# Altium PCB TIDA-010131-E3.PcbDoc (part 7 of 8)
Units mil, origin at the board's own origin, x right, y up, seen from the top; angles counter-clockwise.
Board outline 6889.76 x 5118.11 mil, 6 copper layers (Top Layer, GND Layer, Signal Layer 1, Signal Layer 2, PWR Layer, Bottom Layer), stack 58.5 mil thick; 758 components, 455 nets, 2194 pads, 1156 vias.
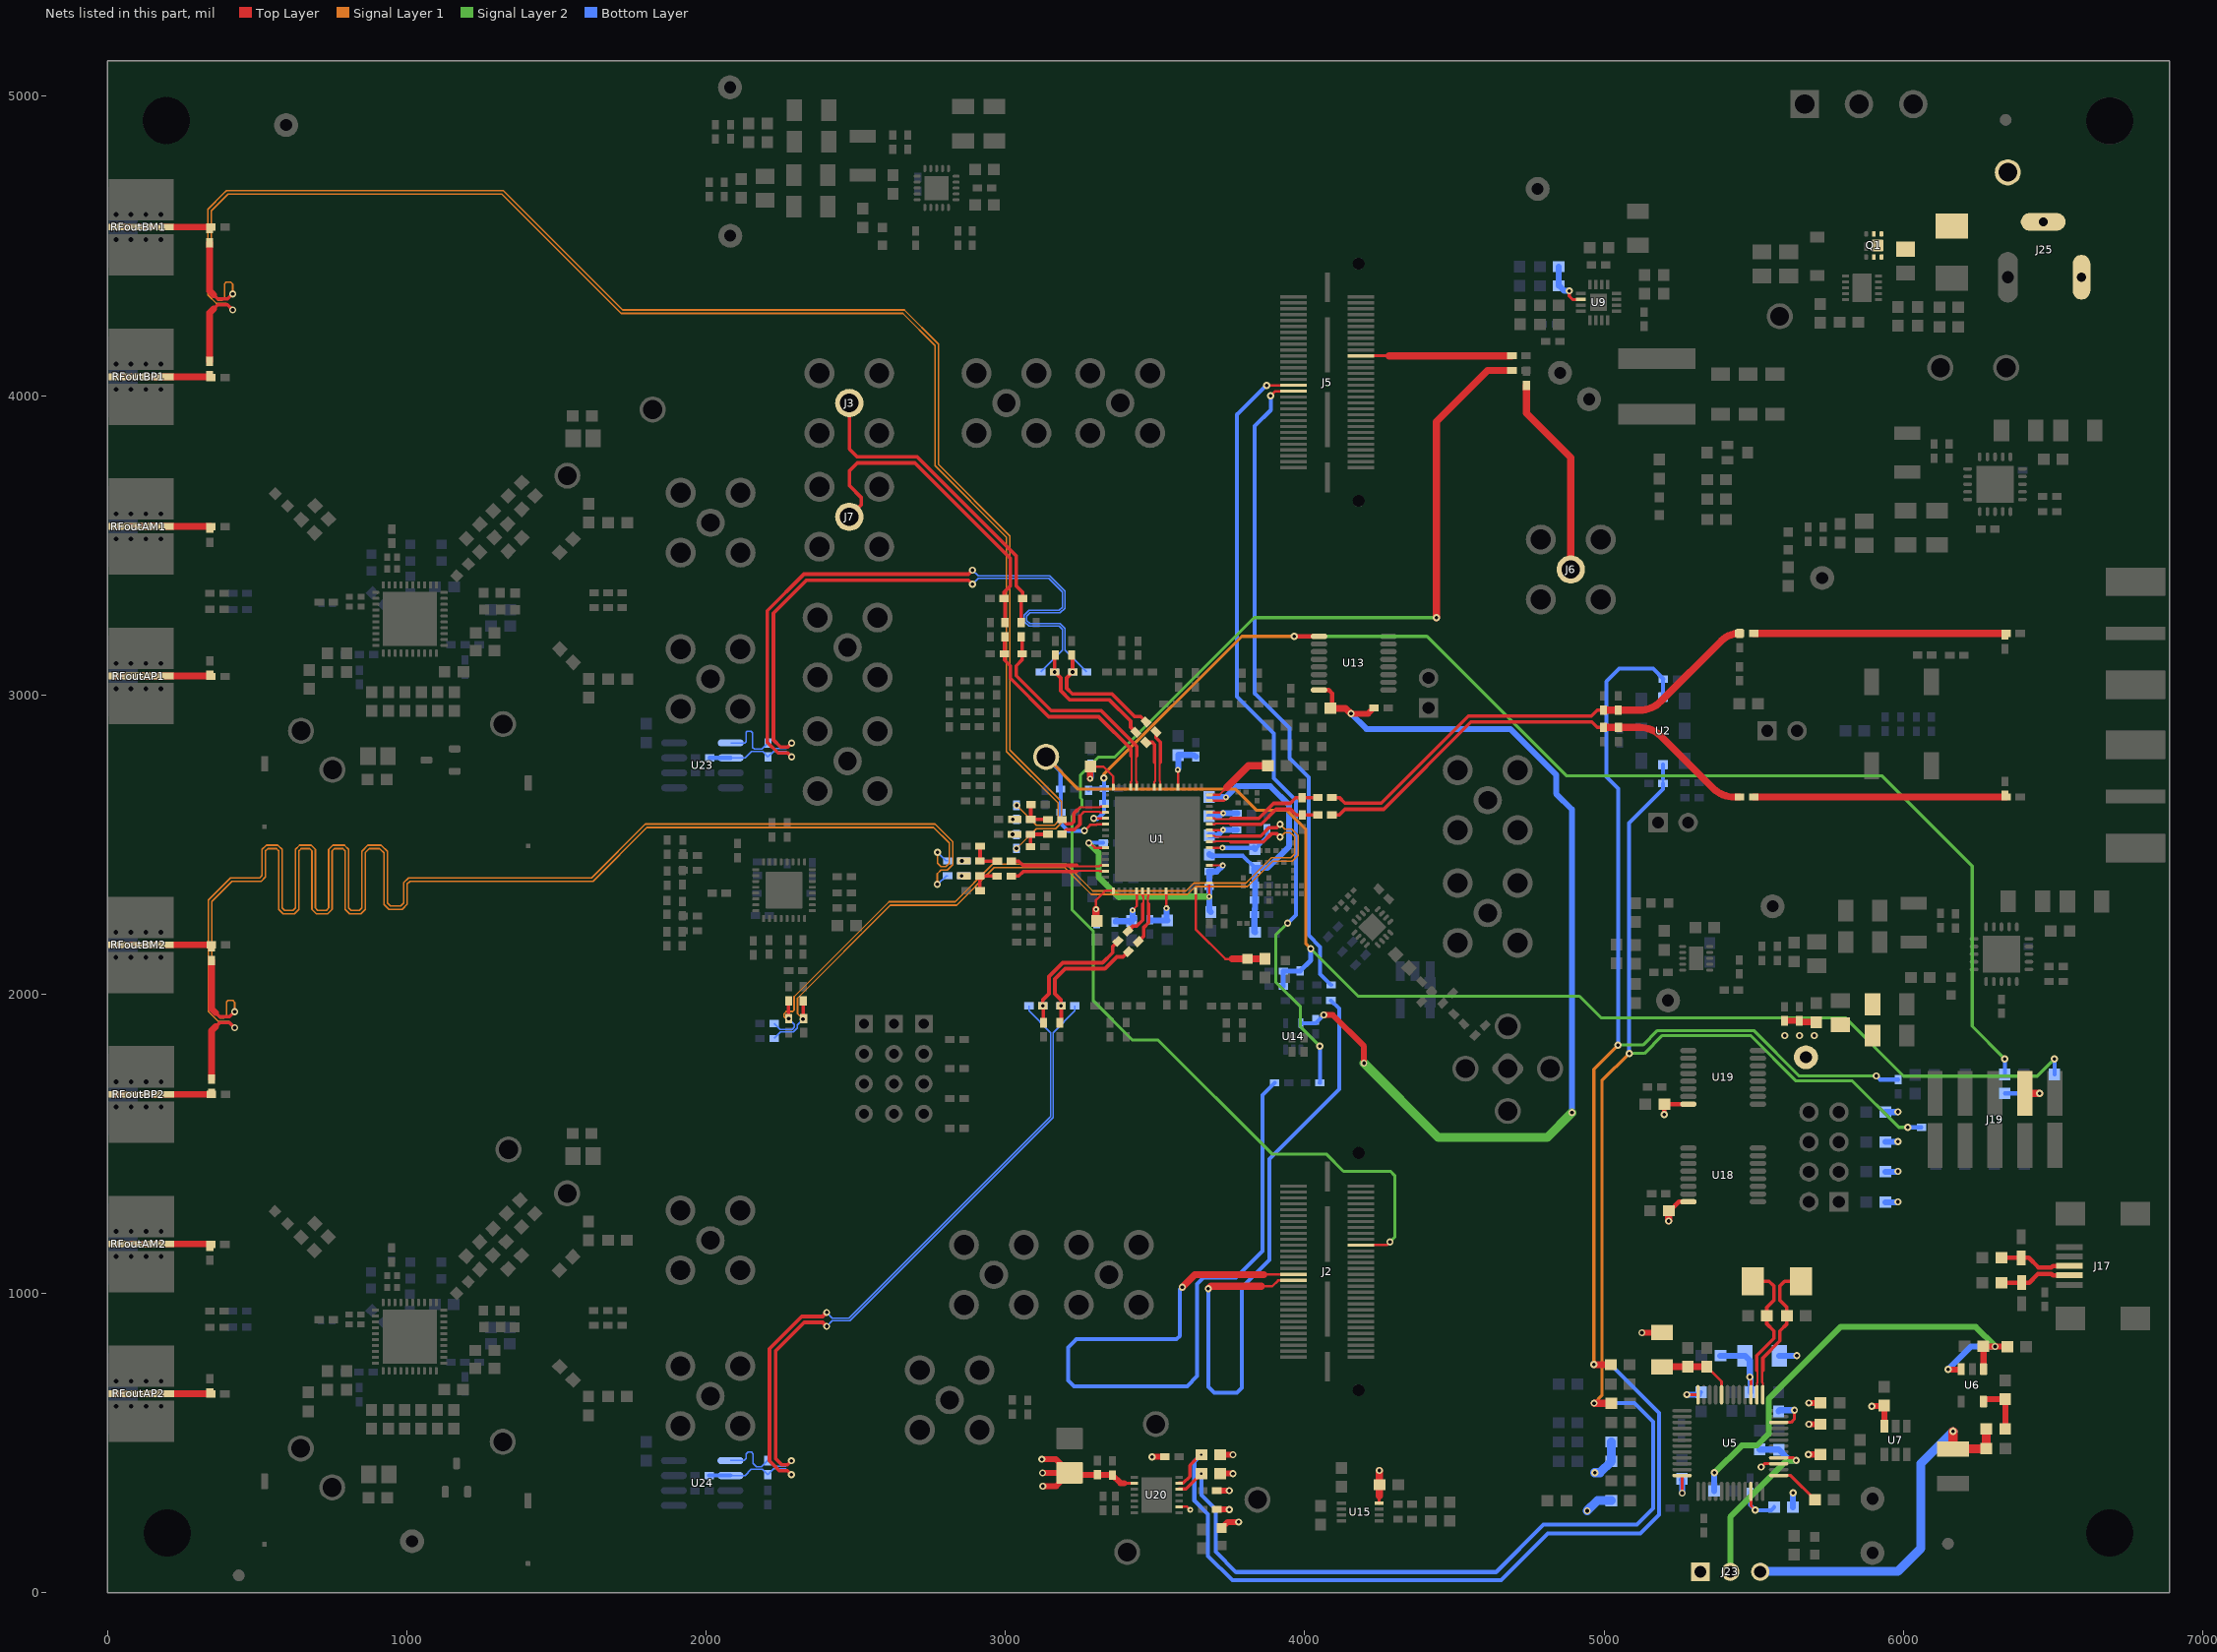
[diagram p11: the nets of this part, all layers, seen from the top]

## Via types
v1: diameter 24, hole 12, Top Layer to Bottom Layer, 726 vias
v2: diameter 32, hole 16, Top Layer to Bottom Layer, 311 vias
v3: diameter 19.68, hole 7.87, Top Layer to Bottom Layer, 117 vias
v4: diameter 25, hole 10, Top Layer to Bottom Layer, 2 vias

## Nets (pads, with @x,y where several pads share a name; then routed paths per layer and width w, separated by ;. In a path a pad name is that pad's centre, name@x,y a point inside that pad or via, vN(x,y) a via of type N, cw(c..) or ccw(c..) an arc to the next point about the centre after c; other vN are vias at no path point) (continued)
OSCI: C125.2 U5.1 Y2.1 | length 485.9
  Top Layer w7: U5.1@5530.47,661.44 5530.47,700.42 5528.13,702.76 5528.13,740.02 5530.63,742.52
  Top Layer w12: 5530.63,742.52 5530.63,784.44 5587.51,841.33 5587.51,874.73 5611.02,898.23 C125.2@5611.02,925.93 5611.02,953.63 5587.51,977.14 5587.51,1025.02 5603.43,1040.93 Y2.1@5658.22,1040.93
OSCIN+: C12.2 R38.2 R40.2 R199.2 | length 1586.9
  Top Layer w12: C12.2@4090.69,2599.1 4115.44,2599.1 4134.32,2617.98 4264.26,2617.98 4555.46,2909.18 4959.31,2909.18 4977.26,2891.22 R40.2@4998.07,2891.22
  Top Layer w24: R40.2@4998.07,2891.22 R199.2@5048.07,2891.22 5119.87,2891.22 cw(c5119.87,2791.22) 5190.58,2861.93 5364.63,2687.89 ccw(c5435.34,2758.6) 5435.34,2658.6 R38.2@5453.07,2658.6 ; R199.2@5047.07,2891.22 R199.2@5047.82,2890.79
OSCIN-: C9.2 C179.2 R34.2 R36.2 R198.2 | length 1597.3
  Top Layer w12: C9.2@4090.69,2656.86 4115.44,2656.86 4134.32,2637.98 4255.98,2637.98 4547.18,2929.18 4957.46,2929.18 4977.26,2948.98 R34.2@4998.07,2948.98
  Top Layer w24: R34.2@4998.07,2948.98 R198.2@5047.07,2948.98 5118.87,2948.98 ccw(c5118.87,3048.98) 5189.58,2978.27 5391.38,3180.07 cw(c5453.07,3118.37) C179.2@5453.07,3205.62
OSCIN_N: C9.1 C11.2 U1.44 | length 393.1
  Top Layer w7: U1.44@3681.05,2587.51 3699.37,2587.51 3701.71,2585.17 3751,2585.17 3753.5,2587.67
  Top Layer w12: 3753.5,2587.67 3846.39,2587.67 3896.4,2637.69 3952.04,2637.69 3970.41,2656.07 C11.2@3991.22,2656.07 4042.66,2656.07 C9.1@4043.45,2656.86
OSCIN_P: C12.1 C22.2 U1.43 | length 392.8
  Top Layer w7: U1.43@3681.05,2567.83 3699.37,2567.83 3701.71,2570.17 3751,2570.17 3753.5,2567.67
  Top Layer w12: 3753.5,2567.67 3854.67,2567.67 3904.69,2617.69 3953.04,2617.69 3971.41,2599.31 C22.2@3992.22,2599.31 4043.24,2599.31 C12.1@4043.45,2599.1
OSCO: C126.1 U5.2 Y2.2 | length 485.9
  Top Layer w7: 5510.63,742.52 5513.13,740.02 5513.13,702.76 5510.78,700.42 U5.2@5510.78,661.44
  Top Layer w12: Y2.2@5496.81,1040.93 5551.6,1040.93 5567.51,1025.02 5567.51,977.14 5544.01,953.63 C126.1@5544.01,925.93 5544.01,898.23 5567.51,874.73 5567.51,849.62 5510.63,792.73 5510.63,742.52
OSCOUT_N: R250.1 R265.2 R269.2 U1.41 | length 2606.1
  Top Layer w7: U1.41@3681.05,2528.46 3699.37,2528.46 3701.71,2526.12 3751,2526.12 3753.5,2528.62
  Top Layer w12: R250.1@2324.82,1977.28 2324.82,1920.03 R269.2@2326.07,1918.78 ; 3753.5,2528.62 3853.33,2528.62 3880.63,2555.91 3906.72,2555.91 v1(3917.97,2567.16)
  Signal Layer 1 w5.5: v1(2323.57,1917.16) 2305.69,1935.03 2305.69,1986.69 2616,2297 2837,2297 2962.5,2422.5 3198.24,2422.5 3287.24,2333.5 3608.5,2333.5 3619,2344 3634.75,2359.75 3808.75,2359.75 3893.5,2444.5 3958.76,2444.5 3978,2463.74 3978,2530.42 3956.76,2551.66 3933.47,2551.66 v1(3917.97,2567.16)
  Bottom Layer w4.25: R265.2@2227.56,1851.91 2249.06,1873.41 2291.21,1873.41 2304.19,1886.38 2304.19,1897.78 v1(2323.57,1917.16)
OSCOUT_P: R244.1 R263.2 R267.2 U1.40 | length 2603.9
  Top Layer w7: U1.40@3681.05,2508.77 3699.37,2508.77 3701.71,2511.12 3751,2511.12 3753.5,2508.62
  Top Layer w12: R244.1@2275.82,1977.28 2275.82,1919.03 R267.2@2276.07,1918.78 ; 3753.5,2508.62 3861.62,2508.62 3888.91,2535.91 3906.72,2535.91 v1(3917.97,2524.66)
  Signal Layer 1 w5.5: v1(2276.32,1917.91) 2267.09,1917.91 2260,1925 2260,1934 2268,1942 2290.19,1942 2294.19,1946 2294.19,1991.46 2611.24,2308.5 2832.24,2308.5 2957.74,2434 3203,2434 3292,2345 3603.74,2345 3629.99,2371.25 3803.99,2371.25 3888.74,2456 3954,2456 3966.5,2468.5 3966.5,2525.66 3952,2540.16 3933.47,2540.16 v1(3917.97,2524.66)
  Bottom Layer w4.25: R263.2@2227.56,1901.91 2247.56,1881.91 2287.69,1881.91 2295.69,1889.91 2295.69,1898.53 v1(2276.32,1917.91)
OUT_N: R36.1 R37.1 R45.2 | length 841.2
  Top Layer w12: R45.2@6334.84,3205.6 R45.2@6339.55,3200.9
  Top Layer w24: R36.1@5500.31,3205.62 R45.2@6334.84,3205.6
OUT_P: R38.1 R39.1 R46.2 | length 842.8
  Top Layer w24: R38.1@5500.31,2658.6 R39.1@6343.15,2658.59
PCLK: J6.1 R260.1 | length 676.7
  Top Layer w24: R260.1@4741,4034.38 4741,3941 4889,3793 J6.1@4889,3419
PCLK1: J5.22 R259.2 | length 504.1
  Top Layer w10: J5.22@4188.32,4132.96 4281.68,4132.96
  Top Layer w24: 4281.68,4132.96 R259.2@4692.38,4133 R259.2@4692.38,4133
PCLK2: J2.22 R261.2 | length 4763.4
  Top Layer w8: J2.22@4188.32,1161.61 4274.93,1161.61 v1(4284.97,1171.66)
  Top Layer w24: v1(4440,3258) 4440,3913 4611,4084 R261.2@4692.38,4084
  Signal Layer 2 w10.5: v1(4284.97,1171.66) 4301,1187.69 4301,1394 4287,1408 4130,1408 4072,1466 3891,1466 3510,1847 3424,1847 3294,1977 3294,2210 3223,2281 3223,2595 3255.85,2627.85 3255.85,2650.59 3251,2655.44 3251,2732 3311,2792 3365,2792 3831,3258 v1(4440,3258)
PGND: C131.2 D8.1 J25.2 J25.3 Q1.1 Q1.2 Q1.5 Q1.6 Q1.8 TP7.1
R_ELMK_SDO: J19.3 R305.2 R311.2 | length 165.2
  Top Layer w24: J19.3@6406,1669 v1(6455,1669)
  Bottom Layer w13.5: R311.2@6339,1668.5 R305.2@6403,1668.5 6454.5,1668.5 v1(6455,1669)
RESET: C184.1 R35.2 R311.1 R343.1 U1.5 U13.9 | length 4502.8
  Top Layer w8: v1(3295,2587.51) U1.5@3334.6,2587.51
  Top Layer w13.5: v1(3965.27,3195.54) U13.9@4047.72,3195.54
  Signal Layer 2 w10.5: v1(3965.27,3195.54) 4408.46,3195.54 4874,2730 5928,2730 6230,2428 6230,1893 v1(6339,1784)
  Signal Layer 1 w10.5: v1(3329,2722) 3329,2734.69 3789.86,3195.54 v1(3965.27,3195.54)
  Bottom Layer w13.5: R343.1@3278,2681.31 3283.35,2686.66 R35.2@3330.35,2686.66 ; v1(3295,2587.51) 3304.43,2587.51 3307.29,2584.66 3329.79,2607.16 C184.1@3329.79,2636.85 ; v1(3329,2722) 3330.35,2720.65 R35.2@3330.35,2686.66 ; C184.1@3329.79,2637.93 C184.1@3329.79,2636.85 ; R311.1@6339,1731.5 v1(6339,1784) ; C184.1@3329.79,2636.85 3330.35,2637.42 R35.2@3330.35,2686.66
RFOUTAM1: C48.1 R84.1 RFoutAM1.1 | length 233.5
  Top Layer w22: RFoutAM1.1@112.65,3562.93 343.46,3562.93 cw(c343.46,3559.45) C48.1@345.92,3561.91
RFOUTAM2: C81.1 R117.1 RFoutAM2.1 | length 235.7
  Top Layer w22: RFoutAM2.1@113.38,1165.1 344.07,1165.1 345.66,1163.51 ccw(c343.2,1161.05) R117.1@343.2,1164.53
RFOUTAP1: C44.1 R81.1 RFoutAP1.1 | length 230.8
  Top Layer w22: RFoutAP1.1@112.65,3063 C44.1@343.46,3063
RFOUTAP2: C77.1 R114.1 RFoutAP2.1 | length 229.7
  Top Layer w22: RFoutAP2.1@113.38,665.1 339.18,665.1 R114.1@341.97,667.89
RFOUTBM1: C57.1 R92.1 RFoutBM1.1 | length 232.7
  Top Layer w22: RFoutBM1.1@112.65,4562.93 C57.1@345.34,4562.93
RFOUTBM2: C90.1 R125.1 RFoutBM2.1 | length 232.7
  Top Layer w22: RFoutBM2.1@112.39,2164.53 R125.1@345.08,2164.53
RFOUTBP1: C64.1 R98.1 RFoutBP1.1 | length 232.7
  Top Layer w22: RFoutBP1.1@112.65,4062.93 345.23,4062.93 C64.1@345.34,4062.82
RFOUTBP2: C97.1 R131.1 RFoutBP2.1 | length 236.5
  Top Layer w22: RFoutBP2.1@113.38,1665.1 344.46,1665.1 R131.1@348.21,1668.85 ; R131.1@344.97,1664.53 R131.1@345.08,1664.42
SCL: R43.1 R172.1 R178.2 R321.1 U2.8 U20.13 | length 6454.5
  Top Layer w11: U20.13@3580.38,366.17 3593.69,366.17 3616.31,388.78 3616.31,425.1 3652.44,461.24 v3(3655.02,461.24)
  Top Layer w24: v1(4966.04,762.5) 4966.52,762.02 R178.2@5022.7,762.02
  Signal Layer 2 w10.5: v1(5047,1830) 5130,1830 5178.5,1878.5 5500.12,1878.5 5651.62,1727 v1(5910,1727)
  Signal Layer 1 w10.5: v1(4966.04,762.5) 4966.04,1749.04 v1(5047,1830)
  Bottom Layer w13.5: v3(3655.02,461.24) 3631.39,437.61 3631.39,307.61 3677,262 3677,123 3758.5,41.5 4656.08,41.5 4812.79,198.21 5122,198.21 5184,260.21 5184,601 5022.5,762.5 v1(4966.04,762.5) ; v1(5047,1830) 5047,2687 5008.25,2725.75 5008.25,3044.41 5051.22,3087.39 5163.66,3087.39 R43.1@5198.45,3052.6 5197.07,3051.22 U2.8@5197.07,2992.6 ; v1(5910,1727) 5922.38,1714.62 R172.1@5983,1714.62
SDA: R44.1 R173.1 R212.2 R320.1 U2.7 U20.12 | length 5865.5
  Top Layer w11: U20.12@3580.38,346.48 3603.26,346.48 v3(3655.02,398.24)
  Top Layer w24: v1(4967.04,633.5) 4967.52,633.02 R212.2@5023.7,633.02
  Signal Layer 2 w10.5: v1(5084,1802) 5135,1802 5195,1862 5489.66,1862 5641.66,1710 5830,1710 5985,1555 v1(6015,1555)
  Signal Layer 1 w10.5: v1(4967.04,633.5) 4993,659.46 4993,1711 v1(5084,1802)
  Bottom Layer w13.5: v3(3655.02,398.24) 3655.02,326.98 3703,279 3703,137 3771,69 4639,69 4798,228 5110,228 5163.75,281.75 5163.75,571.25 5101.5,633.5 v1(4967.04,633.5) ; v1(5084,1802) 5084,2572 5197.07,2685.07 R44.1@5197.07,2703.98 ; 5197.07,2718.79 U2.7@5197.07,2767.01 ; v1(6015,1555) R173.1@6060.38,1555
SDCLKOUT1+: R286.1 U1.3 | length 191.5
  Top Layer w7: 3239.25,2614.54 3249.26,2624.54 3313.94,2624.54 3316.29,2626.88 U1.3@3334.6,2626.88
  Top Layer w12: R286.1@3189.6,2583.66 3204.1,2569.16 3222.16,2569.16 3229,2576 3229,2604.28 3239.25,2614.54
SDCLKOUT1+*: R25.2 R30.2 R286.2 | length 107.8
  Top Layer w7: R30.2@3084.78,2632.85 R30.2@3085.6,2633.66
  Top Layer w12: R30.2@3084.78,2632.85 R25.2@3084.78,2583.78 3142.23,2583.78 R286.2@3142.35,2583.66
SDCLKOUT1-: R287.1 U1.4 | length 193.6
  Top Layer w7: 3249,2596 3262.54,2609.54 3313.94,2609.54 3316.29,2607.2 U1.4@3334.6,2607.2
  Top Layer w12: R287.1@3189.6,2534.66 3204.1,2549.16 3230.44,2549.16 3249,2567.72 3249,2596
SDCLKOUT1-*: R27.2 R29.2 R287.2 | length 107.5
  Top Layer w7: R29.2@3084.41,2492.85 3084.6,2492.66 R29.2@3084.6,2484.66
  Top Layer w12: R29.2@3084.41,2492.85 R27.2@3084.41,2533.78 3141.47,2533.78 R287.2@3142.35,2534.66
SDCLKout1_LMK_N: R98.2 R358.1 | length 5281.6
  Top Layer w12: 354.67,4289.67 368.17,4303.17 401.71,4303.17 v1(418.46,4286.42)
  Top Layer w22: R98.2@341.65,4114.56 341.65,4276.65 354.67,4289.67
  Signal Layer 1 w5.5: v1(418.46,4286.42) 397.46,4307.42 364.32,4307.42 335.5,4336.24 335.5,4622.26 388.74,4675.5 398.15,4684.91 1322.52,4684.91 1721.44,4286 2662.26,4286 2776.5,4171.76 2776.5,3770.26 3015.5,3531.26 3015.5,2815.76 3187.5,2643.76 3187.5,2572.24 3168.3,2553.03 3103.66,2553.03 v1(3037.16,2486.54)
SDCLKout1_LMK_P: R92.2 R359.1 | length 5282.1
  Top Layer w12: 354.67,4336.67 368.17,4323.17 401.71,4323.17 v1(418.46,4339.92)
  Top Layer w22: R92.2@341.65,4510.31 341.65,4349.68 354.67,4336.67
  Signal Layer 1 w5.5: v1(418.46,4339.92) 418.46,4372.54 412,4379 397,4379 391.44,4373.44 391.44,4327.17 383.19,4318.92 369.08,4318.92 347,4341 347,4617.5 402.91,4673.41 1317.76,4673.41 1716.67,4274.5 2657.5,4274.5 2765,4167 2765,3765.5 3004,3526.5 3004,2811 3176,2639 3176,2577 3163.53,2564.53 3104.03,2564.53 v1(3037.54,2631.03)
SDCLKOUT1_N: R27.1 R344.2 R350.1 R358.2
  other v1: 3024,2534
SDCLKOUT1_P: R25.1 R345.2 R351.1 R359.2
  other v1: 3024.38,2584
SDCLKOUT3+: R288.1 U1.13 | length 322.4
  Top Layer w7: 3238.5,2430.19 3241,2427.69 3313.94,2427.69 3316.29,2430.03 U1.13@3334.6,2430.03
  Top Layer w12: R288.1@3020.22,2444.66 3044.97,2444.66 3059.43,2430.19 3238.5,2430.19
SDCLKOUT3+*: R41.2 R50.2 R288.2 | length 107.9
  Top Layer w12: R41.2@2915.2,2445.18 R41.2@2915.6,2444.78 ; R50.2@2915.6,2494.66 R41.2@2915.6,2444.78 ; R288.2@2972.97,2444.66 2915.72,2444.66 R41.2@2915.6,2444.78
SDCLKOUT3-: R289.1 U1.14 | length 323.4
  Top Layer w7: 3238.5,2410.19 3241,2412.69 3313.94,2412.69 3316.29,2410.35 U1.14@3334.6,2410.35
  Top Layer w12: R289.1@3019.6,2394.66 3044.34,2394.66 3059.88,2410.19 3238.5,2410.19
SDCLKOUT3-*: R42.2 R49.2 R289.2 | length 107.1
  Top Layer w7: R49.2@2915.2,2346.06 R49.2@2915.6,2345.66
  Top Layer w12: R49.2@2915.2,2346.06 R42.2@2915.2,2395.18 2915.72,2394.66 R289.2@2972.35,2394.66
SDCLKout3_LMK_N: R131.2 R360.1 | length 5163.9
  Top Layer w12: 361.23,1891.21 374.73,1904.71 408.27,1904.71 v1(425.02,1887.96)
  Top Layer w22: R131.2@348.21,1716.1 348.21,1878.19 361.23,1891.21
  Signal Layer 1 w5.5: v1(425.02,1887.96) 404.48,1908.5 371.24,1908.5 337.5,1942.24 337.5,2314.76 411.74,2389 509.27,2389 517,2396.73 517,2483.53 531.47,2498 569.53,2498 584,2483.53 584,2287.73 591.73,2280 620.27,2280 628,2287.73 628,2483.53 642.47,2498 680.53,2498 695,2483.53 695,2287.73 702.73,2280 731.27,2280 739,2287.73 739,2483.53 753.47,2498 791.53,2498 806,2483.53 806,2287.73 813.73,2280 842.27,2280 850,2287.73 850,2477.67 870.33,2498 914.23,2498 935.5,2476.73 935.5,2304.5 945,2295 979.84,2295 990,2305.16 990,2373 1006,2389 1617.74,2389 1797.24,2568.5 2764.76,2568.5 2823.81,2509.45 2823.81,2432.55 2805.91,2414.65 2785,2414.65 2772.62,2402.27 v1(2772.62,2366.8)
  Bottom Layer w4.25: v1(2772.62,2366.8) 2773.8,2366.8 2802.4,2395.4 R360.1@2807.17,2395.4
SDCLKout3_LMK_P: R125.2 R361.1 | length 5162.6
  Top Layer w12: 361.23,1938.21 374.73,1924.71 408.27,1924.71 v1(425.02,1941.46)
  Top Layer w22: R125.2@348.21,2111.85 348.21,1951.22 361.23,1938.21
  Signal Layer 1 w5.5: v1(425.02,1941.46) 425.02,1972.98 419,1979 403,1979 398,1974 398,1928.71 389.29,1920 376,1920 349,1947 349,2310 416.5,2377.5 514.03,2377.5 528.5,2391.97 528.5,2478.77 536.23,2486.5 564.77,2486.5 572.5,2478.77 572.5,2282.97 586.97,2268.5 625.03,2268.5 639.5,2282.97 639.5,2478.77 647.23,2486.5 675.77,2486.5 683.5,2478.77 683.5,2282.97 697.97,2268.5 736.03,2268.5 750.5,2282.97 750.5,2478.77 758.23,2486.5 786.77,2486.5 794.5,2478.77 794.5,2282.97 808.97,2268.5 847.03,2268.5 861.5,2282.97 861.5,2472.91 875.09,2486.5 909.47,2486.5 924,2471.97 924,2299.74 940.24,2283.5 984.6,2283.5 1001.5,2300.4 1001.5,2368.24 1010.76,2377.5 1622.5,2377.5 1802,2557 2760,2557 2812.31,2504.69 2812.31,2437.31 2801.15,2426.15 2785,2426.15 2773,2438.15 v1(2773,2474)
  Bottom Layer w4.25: v1(2773,2474) 2801.6,2445.4 R361.1@2807.55,2445.4
SDCLKOUT3_N: R42.1 R347.1 R354.1 R360.2
  other v1: 2854.41,2395.4
SDCLKOUT3_P: R41.1 R346.1 R355.1 R361.2
  other v1: 2854.79,2445.4
SDCLKOUT5+: R2.1 R54.2 R59.2 R292.1 | length 451.7
  Top Layer w7: R59.2@3125.63,1960.84 v1(3125.65,1960.89)
  Top Layer w12: R59.2@3125.63,1960.84 3125.63,1981.65 3145.5,2001.53 3145.5,2058.79 3191.72,2105 3324.49,2105 3358.49,2138.99 3358.49,2159.5 R292.1@3375.99,2177 ; R54.2@3127.17,1906.84 R59.2@3127.17,1960.84
SDCLKOUT5+*: R292.2 U1.22 | length 164.6
  Top Layer w7: 3458.46,2301.5 3460.96,2304 3460.96,2324.73 3458.61,2327.08 U1.22@3458.61,2345.39
  Top Layer w12: R292.2@3409.39,2210.4 3426.89,2227.9 3439.29,2227.9 3458.46,2247.07 3458.46,2301.5
SDCLKOUT5-: R10.1 R56.2 R58.2 R293.1 | length 433.9
  Top Layer w12: v1(3185.38,1960.84) 3185.38,1981.65 3165.5,2001.53 3165.5,2050.5 3200,2085 3332.78,2085 3372.63,2124.85 3393.14,2124.85 R293.1@3410.64,2142.35 ; R56.2@3186.93,1908.04 R58.2@3186.93,1960.84
SDCLKOUT5-*: R293.2 U1.23 | length 185.9
  Top Layer w7: U1.23@3478.3,2345.39 3478.3,2327.08 3475.96,2324.73 3475.96,2304 3478.46,2301.5
  Top Layer w12: R293.2@3444.04,2175.76 3461.54,2193.26 3461.54,2221.87 3478.46,2238.78 3478.46,2301.5
SDCLKOUT5_N: R10.2 R281.1 U24.1 | length 2379.3
  Top Layer w12: v1(2285,441.13) 2271.75,427.88 2253,427.88 2232,448.88 2232,807 2328.25,903.25 2389.75,903.25 v1(2403,890)
  Bottom Layer w4.25: U24.1@2081.49,441.5 2127.53,441.5 2134.26,448.23 2134.26,464.24 2139.97,469.96 2151.28,469.96 2157.31,463.92 2157.31,431.81 2168.37,420.75 2185.25,420.75 R281.1@2206,441.5 2225.37,422.13 2266,422.13 v1(2285,441.13) ; v1(2403,890) 2422,909 2481.34,909 3159.72,1587.39 3159.72,1871.13 3232.55,1943.95 R10.2@3232.55,1960.89
SDCLKOUT5_P: R2.2 R280.2 R281.2 U24.2 | length 2449.4
  Top Layer w12: v1(2285,394.63) 2271.75,407.88 2244.72,407.88 2212,440.59 2212,815.28 2319.97,923.25 2389.75,923.25 v1(2403,936.5)
  Bottom Layer w4.25: U24.2@2081.49,391.5 2129.92,391.5 2150.67,412.25 2188.01,412.25 R281.2@2206,394.26 2225.37,413.63 2266,413.63 v1(2285,394.63) ; v1(2403,936.5) 2422,917.5 2477.81,917.5 3151.22,1590.91 3151.22,1871.13 3078.4,1943.95 R2.2@3078.4,1960.89
  Bottom Layer w13.5: R280.2@2010.62,391.5 U24.2@2081.49,391.5
SDCLKOUT11+: R1.1 R3.2 R12.2 R283.2 | length 431.7
  Top Layer w12: R3.2@3221.17,3132.77 3224.75,3129.2 v1(3224.75,3076.4) 3204.87,3056.52 3204.87,3022.13 3224,3003 3356.4,3003 3431.78,2927.62 3452.29,2927.62 R283.2@3469.79,2910.12
SDCLKOUT11+*: R283.1 U1.56 | length 192.9
  Top Layer w7: U1.56@3517.67,2691.84 3517.67,2710.16 3515.33,2712.5 3515.33,2773 3517.83,2775.5
  Top Layer w12: R283.1@3503.19,2876.71 3503.19,2857.09 3517.83,2842.46 3517.83,2775.5
SDCLKOUT11-: R6.2 R9.1 R11.2 R282.2 | length 448.7
  Top Layer w12: R6.2@3167.37,3132.77 3165,3130.4 v1(3165,3076.4) 3184.87,3056.52 3184.87,3013.84 3215.72,2983 3348.12,2983 3418.35,2912.77 3418.35,2892.26 R282.2@3435.84,2874.77
SDCLKOUT11-*: R282.1 U1.57 | length 175.9
  Top Layer w7: 3497.83,2775.5 3500.33,2773 3500.33,2712.5 3497.98,2710.16 U1.57@3497.98,2691.84
  Top Layer w12: R282.1@3469.25,2841.36 3490.64,2841.36 3497.83,2834.17 3497.83,2775.5
SDCLKOUT11_N: R9.2 R133.1 U23.1 | length 2381.1
  Top Layer w12: v1(2286,2839.13) 2272.75,2825.88 2248.91,2825.88 2225,2849.78 2225,3273 2335.25,3383.25 2876.75,3383.25 v1(2890,3370)
  Bottom Layer w4.25: U23.1@2082.49,2839.5 2129.03,2839.5 2133.76,2844.23 2133.76,2874.72 2137.77,2878.73 2151.12,2878.73 2155.81,2874.05 2155.81,2824.51 2161.57,2818.75 2186.25,2818.75 R133.1@2207,2839.5 2226.37,2820.13 2267,2820.13 v1(2286,2839.13) ; v1(2890,3370) 2909,3389 3144.91,3389 3190.62,3343.28 3190.62,3319.24 3190.62,3293.21 3179.84,3282.43 3078.39,3282.43 3062.62,3266.66 3062.62,3245.44 3078.39,3229.68 3179.84,3229.68 3190.62,3218.89 3190.62,3149.27 R9.2@3117.75,3076.4
SDCLKOUT11_P: R1.2 R101.2 R133.2 U23.2 | length 2451.5
  Top Layer w12: v1(2286,2792.63) 2272.75,2805.88 2240.62,2805.88 2205,2841.5 2205,3281.28 2326.97,3403.25 2876.75,3403.25 v1(2890,3416.5)
  Bottom Layer w4.25: U23.2@2082.49,2789.5 2130.92,2789.5 2151.67,2810.25 2189.01,2810.25 R133.2@2207,2792.26 2226.37,2811.63 2267,2811.63 v1(2286,2792.63) ; v1(2890,3416.5) 2909,3397.5 3148.43,3397.5 3199.12,3346.81 3199.12,3319.24 3199.12,3289.69 3183.36,3273.93 3081.91,3273.93 3071.12,3263.14 3071.12,3248.96 3081.91,3238.18 3183.36,3238.18 3199.12,3222.41 3199.12,3149.27 R1.2@3272,3076.4
  Bottom Layer w13.5: R101.2@2012,2789.5 U23.2@2082.49,2789.5
SDCLKOUT13+: R5.2 R14.2 U1.60 | length 777.6
  Top Layer w7: U1.60@3438.93,2691.84 3438.93,2710.16 3436.59,2712.5 3436.59,2794 3439.09,2796.5
  Top Layer w12: R5.2@3052.99,3193.77 3055.57,3191.2 R14.2@3055.57,3137.4 3055.57,3116.59 3036.19,3097.21 3036.19,3064.12 3153.31,2947 3320,2947 3439.09,2827.91 3439.09,2796.5
SDCLKOUT13-: R8.2 R13.2 U1.61 | length 777.3
  Top Layer w7: 3419.09,2796.5 3421.59,2794 3421.59,2712.5 3419.24,2710.16 U1.61@3419.24,2691.84
  Top Layer w12: R8.2@2998.72,3193.77 2996.81,3191.85 R13.2@2996.81,3137.4 2996.81,3116.59 3016.19,3097.21 3016.19,3055.84 3145.03,2927 3311.72,2927 3419.09,2819.63 3419.09,2796.5
SDCLKOUT13_N: J7.1 R8.1 R357.2 | length 1092.1
  Top Layer w12: J7.1@2478.71,3595 2518,3634.29 2518,3660 2478.71,3699.29 2478.71,3748.71 2505,3775 2697.72,3775 3016.5,3456.22 3016.5,3363.69 2995.62,3342.81 R357.2@2995.62,3322 2998.72,3318.9 R8.1@2998.72,3241.01
SDCLKOUT13_P: J3.1 R5.1 R356.2 | length 1093.2
  Top Layer w12: J3.1@2478.71,3975 2478.71,3821.29 2505,3795 2706,3795 3036.5,3464.5 3036.5,3363.69 3057.38,3342.81 R356.2@3057.38,3322 3052.99,3317.61 R5.1@3052.99,3241.02
STATUS_LD1: R53.2 R79.1 U1.31 | length 400.7
  Top Layer w8: U1.31@3635.78,2345.39 3635.78,2217.22 3735.04,2117.96 3757,2117.96
  Top Layer w24: 3757,2117.96 R53.2@3809.19,2117.96 3867.13,2117.96 R79.1@3867.19,2117.89
STATUS_LD2: R80.1 U1.48 | length 235.6
  Top Layer w8: U1.48@3681.05,2666.25 3715.05,2666.25 3740.18,2691.39
  Top Layer w24: 3740.18,2691.39 3812.37,2763.58 R80.1@3876.37,2763.58
SYNC: C185.1 R190.2 R200.2 R201.2 R202.2 R306.1 SYNC.1 U1.6 | length 4718
  Top Layer w8: v1(3264,2546) 3283.51,2565.51 3304.11,2565.51 3306.43,2567.83 U1.6@3334.6,2567.83
  Signal Layer 2 w10.5: v1(4020.15,2151.6) 4178.75,1993 4918,1993 4990,1921 5806,1921 6001,1726 6447,1726 v1(6505,1784)
  Signal Layer 1 w10.5: SYNC.1@3136,2793 3244,2685 3769.16,2685 3840.16,2614 3940,2614 4004,2550 4004,2167.75 v1(4020.15,2151.6)
  Bottom Layer w13.5: SYNC.1@3136,2793 3184.28,2744.72 C185.1@3184.28,2685.06 3185.35,2683.99 R190.2@3185.35,2607.66 3185.35,2570.65 3210,2546 v1(3264,2546) ; R306.1@6505,1731.5 v1(6505,1784)
  Bottom Layer w16: R202.2@3928.65,2025.94 R200.2@3928.65,2076.94 R201.2@3984.4,2076.94 ; R201.2@3985.03,2077.57 4020.15,2112.69 v1(4020.15,2151.6)
SYNC1_IN: J5.31 R192.1 | length 2633.2
  Top Layer w8: v1(3873.31,4034.35) J5.31@3962.72,4034.35
  Signal Layer 2 w10.5: v1(3943,2237) 3903.25,2197.25 3903.25,2040.75 3986,1958 3986,1891 v1(4051,1826)
  Bottom Layer w13.5: v1(3873.31,4034.35) 3871.62,4034.35 3774,3936.74 3774,2994 3897,2871 3897,2721 3970.75,2647.25 3970.75,2264.75 v1(3943,2237) ; R192.1@4050.61,1703.56 4051,1703.95 v1(4051,1826)
SYNC1_OUT: J5.33 R196.1 | length 2178.9
  Top Layer w8: v1(3886.65,3999.62) 3901.69,4014.65 J5.33@3962.72,4014.65
  Bottom Layer w13.5: v1(3886.65,3999.62) 3886.65,3951.65 3833,3898 3833,3005 3949,2889 3949,2788 4013,2724 4013,2197 4052,2158 4052,2067.21 R196.1@4088.27,2030.94
SYNC2_IN: J2.31 R194.1 | length 2657.8
  Top Layer w8: 3863,1063.01 J2.31@3962.72,1063.01
  Top Layer w24: v1(3591,1021) 3633.01,1063.01 3863,1063.01
  Bottom Layer w13.5: v1(3591,1021) 3583,1013 3583,858 3572,847 3237,847 3210,820 3210,710 3230,690 3607,690 3641,724 3641,1032 3662,1053 3770.31,1053 3858.97,1141.66 3858.97,1662.76 R194.1@3899.78,1703.57
SYNC2_OUT: J2.33 R197.1 | length 2191.1
  Top Layer w8: 3856,1024 3892,1024 3911.31,1043.31 J2.33@3962.72,1043.31
  Top Layer w24: v1(3677.97,1015.66) 3686.31,1024 3856,1024
  Bottom Layer w13.5: v1(3677.97,1015.66) 3677.97,688.03 3698,668 3773,668 3789.97,684.97 3789.97,1019.66 3881.97,1111.66 3881.97,1449.66 4115,1682.69 4115,1951.59 R197.1@4087.65,1978.94
USB_DM: D12.2 J17.2 R149.1 | length 241.4
  Top Layer w15: R149.1@6327.5,1036 D12.2@6395,1036.04 6420.46,1036.04 6449.68,1065.26 6495.23,1065.26 6499.97,1060.51 J17.2@6554.76,1060.51
  Top Layer w24: R149.1@6327.5,1036 R149.1@6327.5,1036
USB_DP: D7.2 J17.3 R150.1 | length 242.4
  Top Layer w15: R150.1@6327.5,1119 D7.2@6394,1118.96 6419.46,1118.96 6451.17,1087.26 6495.23,1087.26 6499.97,1092 J17.3@6554.76,1092
  Top Layer w24: R150.1@6327.5,1119 R150.1@6327.5,1119
USB_RESET: C116.1 R155.1 U5.34 | length 202.9
  Top Layer w10: U5.34@5491.1,338.6 5491.1,290.12 v1(5505.2,276.02)
  Bottom Layer w13.5: C116.1@5488.2,335.77 5488.2,293.02 v1(5505.2,276.02) 5558.7,276.02 R155.1@5568.7,286.02
V_BUS: C119.1 C120.2 J23.3 L17.2 | length 1247.7
  Top Layer w30: v1(6166,539) 6166.26,538.74 C119.1@6166.26,479.4 6168.26,481.4 C120.2@6277.77,481.4 6277.31,481.86 L17.2@6277.31,547.85
  Bottom Layer w30: J23.3@5522,84 5535,71 5981,71 6059,149 6059,432 v1(6166,539)
VBUS: C121.1 R147.2 R148.2 U6.1 U6.3 | length 1685.3
  Top Layer w20: v1(6150,746) 6191.96,746 U6.3@6193.09,747.13 ; U6.1@6267.9,747.13 6267.9,822.09 C121.1@6266.99,823 v1(6306.75,823) 6346.5,823 R148.2@6347.5,822
  Signal Layer 2 w20: v1(5369.2,401.02) 5460.18,492 5511,492 5550,531 5550,648 5790,888 6241.75,888 v1(6306.75,823)
  Bottom Layer w20: R147.2@5368.7,340.02 5368.7,400.52 v1(5369.2,401.02) ; v1(6150,746) 6227,823 v1(6306.75,823)
VBUSS: C118.1 L17.1 U6.5 | length 174.5
  Top Layer w20: U6.5@6267.9,638.87 6275.54,646.5 C118.1@6340.5,646.5 6340.5,548.04 L17.1@6340.3,547.85
VCC1_VCO: C34.1 C35.1 C36.1 L7.2 U1.10 U1.33 U1.36 | length 925.6
  Top Layer w8: v1(3278.57,2505.28) 3282.15,2505.28 3298.34,2489.09 U1.10@3334.6,2489.09 ; v3(3681,2326) 3681,2323.19 3681.05,2323.14 U1.33@3681.05,2370.98 ; U1.36@3681.57,2430.28 v3@3726.09,2430.28
  Signal Layer 2 w20: v1(3278.57,2505.28) 3311.5,2472.36 3311.5,2391.5 3380,2323 3383,2326 v3(3681,2326)
  Bottom Layer w13.5: v1(3278.57,2505.28) 3278.68,2505.39 C36.1@3327.1,2505.39
  Bottom Layer w20: L7.2@3686.57,2274.28 3681,2279.85 v3(3681,2326) 3681,2359.59 C35.1@3681.2,2359.78 3681.2,2408.78 C34.1@3680.2,2409.78 3705.9,2409.78 v3(3726.09,2429.97)
VCC2_CG1: C26.1 L1.2 U1.17 | length 189.9
  Top Layer w8: L1.2@3302.97,2247.66 L1.2@3305.57,2245.06 ; v3(3302.97,2283.66) 3302.97,2314.64 3333.72,2345.39 U1.17@3360.19,2345.39
  Top Layer w24: L1.2@3302.97,2247.66 v3(3302.97,2283.66)
  Bottom Layer w20: v3(3302.97,2283.66) 3302.97,2238 C26.1@3305.57,2235.4
VCC3_SYSREF: C28.1 L2.2 U1.21 | length 176.5
  Top Layer w8: v3(3425,2280) 3425,2280.66 3438.93,2294.59 U1.21@3438.93,2345.39
  Bottom Layer w13.5: C28.1@3365.72,2240.01 C28.1@3369.6,2243.88 ; L2.2@3420.57,2243.88 L2.2@3421.72,2243.88 L2.2@3422.57,2244.73
  Bottom Layer w20: C28.1@3369.6,2243.88 3420.57,2243.88 L2.2@3420.57,2238.4 ; L2.2@3422.57,2244.73 3430.72,2252.88 3425,2258.61 v3(3425,2280)
VCC4_CG2: C31.1 L3.2 U1.26 | length 160.7
  Top Layer w8: U1.26@3537.35,2345.39 3537.35,2288.04 v3(3538.22,2287.18)
  Bottom Layer w20: C31.1@3482.57,2248.4 3484.7,2246.28 L3.2@3541.57,2246.28 3538.22,2249.63 v3(3538.22,2287.18)
VCC7_OSCOUT: C189.1 L6.2 U1.39 | length 239.2
  Top Layer w8: U1.39@3681.05,2489.09 3725.57,2489.09 v3(3725.57,2488.78)
  Bottom Layer w13.5: v3(3725.57,2488.78) L6.2@3830.32,2488.78 ; L6.2@3833.97,2485.12 3873.97,2525.12 C189.1@3873.97,2553.04
  Bottom Layer w20: L6.2@3830.32,2488.78 L6.2@3833.97,2485.12
VCC8_OSCIN: C190.2 L9.2 U1.42 | length 145.4
  Top Layer w8: U1.42@3681.05,2548.14 v3@3726.99,2548.14
  Bottom Layer w20: L9.2@3681.57,2530.28 3709.13,2530.28 v3(3727.57,2548.73) 3727.64,2548.66 C190.2@3773.35,2548.66
VCC9_CP2: C191.2 L10.2 U1.45 | length 146
  Top Layer w8: U1.45@3681.05,2607.2 3726.99,2607.2 3727.97,2606.22 v3(3727.97,2604.66)
  Bottom Layer w20: L10.2@3681.05,2595.39 3715.18,2595.39 3724.45,2604.66 v3(3727.97,2604.66) C191.2@3774.35,2604.66
VCC10_PLL2: C37.1 C38.1 C39.1 L6.1 L8.2 L9.1 L10.1 U1.47 | length 1040.5
  Top Layer w8: U1.47@3681.05,2646.57 3730.36,2646.57 3736.97,2653.18 v3(3736.97,2657.66)
  Bottom Layer w13.5: L9.1@3693.65,2462.29 3793.82,2462.29 L6.1@3833.97,2422.13
  Bottom Layer w20: L10.1@3681.05,2658.38 3736.25,2658.38 3772.53,2694.66 3885.34,2694.66 3948,2632 3948,2494 3876.13,2422.13 L6.1@3833.97,2422.13 3831.95,2420.11 3834.18,2364.87 3834.95,2345.78 3834.95,2295.78 C37.1@3831.95,2265.78 3831.95,2208.91 L8.2@3834.08,2206.78 ; L9.1@3681.57,2467.29 ccw(c3693.65,2479.36) L9.1@3693.65,2462.29
VCC11_CG3: C32.1 L4.2 U1.53 | length 168.8
  Top Layer w8: v3(3575.86,2750.06) 3576.72,2749.19 U1.53@3576.72,2691.84
  Bottom Layer w20: v3(3575.86,2750.06) ccw(c3571.71,2754.2) 3577.57,2754.2 L4.2@3577.57,2799.29 3623,2799.29 cw(c3623,2780.09) C32.1@3636.57,2793.66
VCC12_CG0: C33.1 L5.2 U1.64 | length 214.3
  Top Layer w8: L5.2@3284.69,2760.01 3327.99,2760.01 3360.19,2727.81 U1.64@3360.19,2691.84
  Top Layer w9.84: L5.2@3283.19,2756.39 cw(c3288.31,2756.39) L5.2@3284.69,2760.01
  Top Layer w20: v3(3283,2720) 3283,2756.2 L5.2@3283.19,2756.39
  Bottom Layer w20: v3(3283,2720) 3285.69,2722.69 C33.1@3285.69,2767.88
VCCA: C115.2 U5.37 | length 154.5
  Top Layer w10: U5.37@5583.62,391.75 5623.97,391.75 C115.2@5704.7,311.02
VDDD33: C1.2 C2.1 C23.2 C108.1 C109.1 C110.1 C124.2 C142.1 C143.2 C144.1 C145.1 C198.2 C199.1 C200.1 C201.1 C202.1 D16.1 J23.1 L15.1 L16.1 L18.2 L20.2 R151.2 R152.2 R155.2 R160.2 R161.2 R162.2 R205.2 R209.2 R308.1 R309.1 R310.1 R312.1 R316.2 R317.2 R318.2 R320.2 R321.2 TP8.1 U5.12 U5.24 U5.39 U5.46 U7.6 U13.16 U14.5 U15.8 U18.16 U19.16 U20.2 U20.9 | length 5847.3
  Top Layer w8: U20.9@3580.38,287.43 3607.57,287.43 v3(3618,277)
  Top Layer w10: 3397.37,366.17 U20.2@3430.77,366.17 ; U15.8@4249,299.23 4249,322.99 4249.5,323.5 ; v1@5260.78,333.22 U5.24@5260.78,391.75 ; v1(5277.2,662.02) 5284.2,662.02 5284.78,661.44 U5.12@5313.93,661.44 ; v1(5525.2,420.02) 5536.3,431.12 U5.39@5583.62,431.12 ; U5.46@5583.62,568.92 5625.1,568.92 5636.2,580.02 v1(5636.2,610.02)
  Top Layer w15: U13.16@4047.72,3016.41 4080.14,3016.41 4091,3005.55 4091,2960.5 C1.2@4085.5,2955 ; v1(5201.5,1598) C198.2@5201.5,1632.93 5202,1632.43 U19.16@5281.86,1632.43 ; C23.2@5216.5,1276.66 5220.66,1276.66 5250.41,1306.41 U18.16@5282,1306.41
  Top Layer w20: v1(3122.31,446.1) 3168.79,446.1 C201.1@3214.51,400.38 ; v1(3124.31,400.1) 3124.03,400.38 C201.1@3214.51,400.38 ; v1(3125.31,356.1) 3170.24,356.1 C201.1@3214.51,400.38 ; 3397.37,366.17 3384.58,366.17 C202.1@3357.51,393.24 3308.51,393.24 C200.1@3307.51,394.24 3220.65,394.24 C201.1@3214.51,400.38 ; v1(3490.31,454.1) 3490.44,454.24 R318.2@3532.89,454.24 ; R316.2@3706.13,278.24 v1(3748.58,278.24) ; R317.2@3706.13,341.24 v1(3748.58,341.24) ; R320.2@3718.01,398.24 3760.46,398.24 v1(3760.59,398.37) ; R321.2@3718.01,461.24 3760.46,461.24 v1(3760.59,461.37) ; D16.1@3722.51,216.29 3742.5,236.28 v1(3779.41,236.28) ; v1(4063.99,1930.66) 4093.34,1930.66 4197.97,1826.03 v1(4197.97,1769.66) ; v1(4155,2937) 4211.71,2937 R209.2@4231.1,2956.39 ; v1(5126.2,869.02) 5126.29,869.1 L16.1@5194.2,869.1 ; C145.1@5602.62,1910.85 C144.1@5652.62,1910.85 5656.72,1906.75 C143.2@5709.43,1906.75 ; v1(5683.2,462.02) R160.2@5722.7,462.02 ; v1(5684.2,563.02) R162.2@5723.7,563.02 ; v1(5684.2,634.02) R161.2@5723.7,634.02 ; v1(5895.2,623.11) 5895.7,623.62 C124.2@5936.2,623.62 ; C124.2@5936.2,625.52 5936.8,624.92 U7.6@5936.8,556.26
  Top Layer w24: C1.2@4085.5,2955 4137,2955 v1(4155,2937) ; 4249.5,323.5 C199.1@4249.5,361 v1(4249.5,408.5) ; v1(5215.69,1242) C23.2@5215.69,1276.66
  Signal Layer 2 w30: v1(4197.97,1769.66) 4446.63,1521 4810,1521 v1(4893,1604)
  Bottom Layer w13.5: U14.5@3987.56,1903.23 4036.56,1903.23 v1(4063.99,1930.66) ; C109.1@5258.86,378.02 C109.1@5260.78,379.94 ; C108.1@5316.7,662.02 C108.1@5324.2,669.51
  Bottom Layer w20: v1(4155,2937) 4206,2886 4687,2886 4840,2733 4840,2670 4893,2617 v1(4893,1604) ; C109.1@5258.86,378.02 5261,375.88 v1(5261,333) ; v1(5277.2,662.02) C108.1@5316.7,662.02 ; C110.1@5583.2,606.52 5586.7,610.02 v1(5636.2,610.02) ; L15.1@5585.29,792.02 v1(5644.2,792.02) ; R155.2@5631.7,286.02 5631.7,333.51 v1(5632.2,334.02) ; R308.1@5939.5,1305 5980.87,1305 v1(5981.87,1306) ; R309.1@5939.5,1407 5980.87,1407 v1(5981.87,1408) ; R310.1@5939.5,1506 5980.87,1506 v1(5981.87,1507) ; R312.1@5939.5,1606 5980.87,1606 v1(5981.87,1607)
  Bottom Layer w30: v1(4944,274) 4978.02,308.02 R205.2@5024.7,308.02 ; v1(4969,401) 4986.19,401 R152.2@5024.7,439.52 R151.2@5024.7,504.02
  other v1: 5604.19,1861.5 5653.19,1861.5 5702.19,1861.5
VPHY: C107.2 C111.1 L15.2 U5.3 | length 272.6
  Top Layer w10: v1(5487.2,721.02) 5491.1,717.12 U5.3@5491.1,661.44
  Bottom Layer w20: C111.1@5388.7,792.02 L15.2@5471.11,792.02 5487.2,775.93 v1(5487.2,721.02) 5489.2,719.02 C107.2@5489.2,670.51
VPLL: C112.1 C114.1 L16.2 U5.8 | length 263.8
  Top Layer w10: C112.1@5343.2,755.52 5392.67,706.05 U5.8@5392.67,661.44
  Top Layer w24: L16.2@5194.2,754.93 5194.79,755.52 C114.1@5280.2,755.52 C112.1@5343.2,755.52
VREGIN: C106.1 C117.1 J23.2 U5.40 | length 680.8
  Top Layer w10: U5.40@5583.62,450.81 5633.41,450.81 v1(5642.2,442.02)
  Signal Layer 2 w20: J23.2@5422,70 5422,253 5611.02,442.02 v1(5642.2,442.02)
  Bottom Layer w20: C117.1@5520.2,478.52 5583.46,478.52 C106.1@5583.62,478.36 5619.96,442.02 v1(5642.2,442.02)
VSNS: R229.1 R230.2 U9.6 | length 169.9
  Top Layer w10: v1(4884,4350) 4884,4332 4894.54,4321.46 U9.6@4922.47,4321.46
  Bottom Layer w20: R230.2@4848.47,4430.66 R229.1@4848.47,4368.53 ; v1(4884,4350) 4867,4350 R229.1@4850.34,4366.66 ; R229.1@4848.47,4368.53 R229.1@4850.34,4366.66 ; R229.1@4848.47,4368.53 R229.1@4848.47,4366.66 R229.1@4850.34,4366.66
pads on no net: FID1.1 FID2.1 FID3.1 FID4.1 FID5.1 FID6.1 J2.1 J2.20 J2.28 J2.30 J2.36 J2.38 J2.44 J2.46 J2.52 J2.54 J2.MH1 J2.MH2 J5.1 J5.20 J5.28 J5.30 J5.36 J5.38 J5.44 J5.46 J5.52 J5.54 J5.MH1 J5.MH2 J17.4 J19.7 LBL1.0 Q1.0 S1.1 S2.1 S3.1 S4.1 S5.3 U1.8 U1.9 U2.1 U2.2@5124.24,2864.06 U2.2@5124.24,2895.55 U2.3@5124.24,2964.06 U2.3@5124.24,2995.55 U2.4@5269.91,2964.06 U2.4@5269.91,2995.55 U2.5@5269.91,2864.06 U2.5@5269.91,2895.55 U2.6@5269.91,2764.06 U2.6@5269.91,2795.55 U5.27 U5.28 U5.29 U5.30 U5.33 U6.4 U8.9 U9.14 U10.2 U10.4 U10.5 U10.6 U10.9 U10.10 U10.17 U10.18 U10.19 U11.2 U11.4 U11.5 U11.6 U11.9 U11.10 U11.17 U11.18 U11.19 U12.5 U12.7 U12.9 U16.11 U16.12 U16.18 U16.19 U16.21 U16.22 U16.25 U16.26 U16.27 U16.29 U16.31 U18.12 U18.13 U18.14 U19.12 U19.13 U19.14 U20.1 U20.3 U20.4 U21.3

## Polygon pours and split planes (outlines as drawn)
GND on Top Layer "h" (solid, remove dead copper, pour order 446): 282.85,35 63.5,35 25,73.5 25,5023.5 77,5075.5 6717,5075.5 6840.5,4952 6853.85,4938.65 6853.85,4240 6853.85,111 6777.85,35
GND on Top Layer "h" (solid, remove dead copper, pour order 444): 1274.74,1372.6 1274.74,1277.6 708.74,711.6 482.74,485.6 90.74,485.6 19.74,485.6 2.74,502.6 2.74,2330.6 72.74,2400.6 1206.74,2400.6 1275.74,2331.6
GND on Top Layer "h" (solid, remove dead copper, pour order 430): 4813,4163 4636,4163 4624,4175 4624,4377 4641,4394 4877,4394 4891,4408 4909,4408 4924,4393 4924,4342.69 4922.47,4341.16 4703.29,4341.16 4692.77,4330.64 4686,4323.87 4686,4228 4686,4204 4694,4196 4821,4196 4824,4193 4824,4168 4819,4163
+3.3V_LMX on Top Layer "PWR Layer-No Net" (solid, remove dead copper, pour order 419): 2011,4681 2241,4681 2247,4687 2248,4688 2248,4772 2258,4782 2331,4782 2337,4776 2337,4578 2325,4566 2204,4566 2192,4554 2192,4491 2181,4480 2174,4473 2096,4473 1998,4473 1984,4487 1984,4675 1990,4681 1994,4681
+3.3V_LMXRF on Top Layer "PWR Layer-No Net" (solid, remove dead copper, pour order 418): 2011,4888 2238,4888 2248,4878 2248,4814 2255,4807 2333,4807 2337,4811 2337,4996 2325,5008 2214,5008 2208,5014 2208,5065 2190,5083 2185,5088 2032,5088 2023,5088 2005,5070 2005,4893 2010,4888
NetC155_1 on Top Layer "h" (solid, remove dead copper, pour order 410): 2759,4750 2759,4830 2753,4836 2750,4839 2677,4839 2603,4839 2600,4836 2600,4788 2595,4783 2460,4783 2452,4791 2452,4887.78 2446.78,4893 2383,4893 2377,4887 2377,4697 2380,4694 2563,4694 2576,4707 2581,4712 2646,4712 2712,4712 2719,4719 2719,4737 2725,4743 2754,4743 2759,4748
NetC154_1 on Top Layer "h" (solid, remove dead copper, pour order 409): 3001.79,4879.15 2819.79,4879.15 2784.79,4844.15 2784.79,4765.52 2784.79,4746.15 2786.79,4744.15 2819.79,4744.15 2821.79,4742.15 2822.79,4741.15 2822.79,4723.15 2822.79,4710.15 2824.79,4708.15 2856.88,4708.15 2876.79,4728.06 2916.69,4728.06 2921.79,4733.15 2921.79,4801.15 2931.79,4811.15 3011.79,4811.15 3016.79,4816.15 3016.79,4873.15 3010.79,4879.15
GND on Top Layer "h" (solid, remove dead copper, pour order 429): 5610.4,4040.46 5350,4040.46 5334.45,4056 5334.45,4368.55 5245,4458 5217,4486 5217,4609 5217,4686 5187,4716 5002,4716 4979,4693 4972.74,4686.74 4972.74,4516.9 4972.74,4348.9 4979.97,4341.66 5007.49,4341.66 5010.97,4338.18 5010.97,4286.97 5005,4281 4956.63,4281 4952.97,4284.66 4952.97,4329.66 4950.6,4332.04 4910.11,4332.04 4890.97,4351.17 4890.97,4749.97 4925,4784 4939,4798 5038,4798 5246,4798 5300,4744 5300,4537 5376,4461 5409,4428 5409,4291 5409,4170 5431,4148 5442,4137 5539,4137 5631,4137 5643,4125 5643,4049.92 5633.54,4040.46
+3.3VLMK on Top Layer "h" (solid, remove dead copper, pour order 426): 5835,2132 5776,2132 5762,2146 5508,2146 5499,2155 5499,2335 5514,2350 5827,2350 5838,2339 5838,2135 5835,2132
GND on Top Layer "h" (solid, remove dead copper, pour order 425): 6066.91,4263.57 6070.91,4259.57 6070.91,4175.57 6063.91,4168.57 5834.91,4168.57 5824.91,4178.57 5824.91,4448.57 5810.91,4462.57 5441.91,4462.57 5433.91,4470.57 5433.91,4640.57 5447.91,4654.57 5736.43,4654.57 5883,4508 5883,4310 5929.43,4263.57 6064.43,4263.57
GND on Top Layer "PWR Layer-No Net" (solid, remove dead copper, pour order 422): 5387,3721 5387,3555 5390,3552 5466,3552 5470,3556 5470,3729 5441,3758 5436,3763 5436,3831 5436,3848 5431,3853 5393,3853 5390,3850 5387,3847 5387,3721
+3.3V_ALL on Top Layer "PWR Layer-No Net" (solid, remove dead copper, pour order 421): 5233,3817 5233,3564 5243,3554 5353,3554 5364,3565 5364,3836 5358,3842 5246,3842 5233,3829
NetC42_1 on Top Layer "PWR Layer-No Net" (solid, remove dead copper, pour order 420): 5593,3981 5045,3981 5038,3974 5038,3892 5047,3883 5442,3883 5453,3872 5453,3776 5462,3767 5598,3767 5610,3779 5610,3964
+3.3V_VCO on Top Layer "PWR Layer-No Net" (solid, remove dead copper, pour order 417): 6155,3528 5670,3528 5662,3520 5662,3341 5669,3334 5673,3330 5728,3330 5825,3330 5908,3413 6149,3413 6163,3427 6163,3520 6155,3528
VDDD33 on Top Layer "PWR Layer-No Net" (solid, remove dead copper, pour order 415): 5932,2011 5863,2011 5856,2004 5856,1937 5847,1928 5608,1928 5583,1928 5575,1920 5575,1734 5584,1725 5915,1725 5923,1733 5937,1747 5937,1924 5937,2006 5932,2011
NetC61_2 on Top Layer "h" (solid, remove dead copper, pour order 398): 978.5,3455.86 978.5,3518.45 974.09,3522.86 929.09,3522.86 927.09,3520.86 924.09,3517.86 924.09,3449.86 924.09,3446.86 925.09,3445.86 976.5,3445.86 978.5,3447.86
NetC94_2 on Top Layer "h" (solid, remove dead copper, pour order 399): 977.93,1053.37 977.93,1115.96 973.52,1120.37 928.52,1120.37 926.52,1118.37 923.52,1115.37 923.52,1047.37 923.52,1044.37 924.52,1043.37 975.93,1043.37 977.93,1045.37
NetC45_2 on Top Layer "h" (solid, remove dead copper, pour order 400): 806.6,3338.28 744.01,3338.28 739.6,3333.87 739.6,3288.87 741.6,3286.87 744.6,3283.87 812.6,3283.87 815.6,3283.87 816.6,3284.87 816.6,3336.28 814.6,3338.28
NetC78_2 on Top Layer "h" (solid, remove dead copper, pour order 401): 805.84,940.38 743.25,940.38 738.84,935.97 738.84,890.97 740.84,888.97 743.84,885.97 811.84,885.97 814.84,885.97 815.84,886.97 815.84,938.38 813.84,940.38
NetC135_1 on Top Layer "h" (solid, remove dead copper, pour order 402): 6279.43,2256.25 6221.03,2256.25 6201.68,2236.9 6087.08,2236.9 6075.43,2225.25 6072.07,2221.89 5923.49,2221.89 5897.07,2221.89 5892.43,2217.25 5892.43,2125.25 5898.43,2119.25 5974.43,2119.25 5983.43,2110.25 5983.43,1930.2 5988.97,1924.66 6041.97,1924.66 6048.92,1931.61 6048.92,2115.74 6058.43,2125.25 6251.43,2125.25 6254.43,2128.25 6254.43,2198.47 6266.47,2210.5 6281.68,2210.5 6284.43,2213.25 6284.43,2251.25
5VIN on Top Layer "h" (solid, remove dead copper, pour order 403): 5811.66,4352.3 5675.66,4352.3 5664.66,4341.3 5664.66,4179.3 5654.66,4169.3 5464.7,4169.3 5437.66,4196.34 5437.66,4418.3 5447.66,4428.3 5811.39,4428.3 5818.66,4421.04 5818.66,4355.3 5815.66,4352.3
NetC134_1 on Top Layer "h" (solid, remove dead copper, pour order 404): 6375.68,2258.9 6421.45,2258.9 6434.8,2272.25 6434.8,2352.99 6441.43,2359.63 6572.43,2359.63 6578.43,2353.63 6578.43,2264.63 6574.43,2260.63 6523.81,2260.63 6514.43,2251.25 6514.43,2134.25 6505.43,2125.25 6406.43,2125.25 6401.91,2129.78 6401.91,2204.78 6398.43,2208.25 6374.43,2208.25 6370.85,2211.83 6370.85,2254.07
NetC138_1 on Top Layer "h" (solid, remove dead copper, pour order 405): 6353,3830.5 6401.36,3830.5 6413.36,3842.5 6413.36,3923.24 6420,3929.88 6551,3929.88 6557,3923.88 6557,3834.88 6553,3830.88 6502.38,3830.88 6493,3821.5 6493,3704.5 6484,3695.5 6385,3695.5 6380.47,3700.03 6380.47,3775.03 6377,3778.5 6353,3778.5 6349.42,3782.08 6349.42,3826.92 6353,3830.5
NetC139_1 on Top Layer "h" (solid, remove dead copper, pour order 406): 6229.57,3696.58 6063.74,3696.58 6049.73,3682.57 6049.73,3593.8 6043.43,3587.5 5971,3587.5 5967.5,3587.5 5959,3596 5959,3800 5969.5,3810.5 6177,3810.5 6193,3826.5 6258,3826.5 6263,3821.5 6263,3783.5 6259,3779.5 6257.42,3777.92 6232.46,3777.92 6232.46,3698.87
NetC40_1 on Top Layer "h" (solid, remove dead copper, pour order 407): 4984.97,4379.66 4984.97,4537.66 5008.97,4561.66 5155.98,4561.66 5168.97,4548.66 5168.97,4445.66 5168.97,4385.66 5161.97,4378.66 5104.97,4378.66 5059.97,4333.66 5023.97,4333.66 5022.97,4334.66 5022.97,4351.66 5020.97,4353.66 4986.97,4353.66 4984.97,4355.66
NetC41_2 on Top Layer "h" (solid, remove dead copper, pour order 408): 4965.97,4267.66 4965.97,4213.66 4975.97,4203.66 5023.45,4203.66 5042.97,4184.14 5042.97,4084.66 5047.97,4079.66 5306.97,4079.66 5314.97,4087.66 5314.97,4206.66 5287.97,4233.66 5272.97,4248.66 5144.97,4248.66 5037.97,4248.66 5017.97,4268.66 4966.97,4268.66
GND on Top Layer "h" (solid, remove dead copper, pour order 443): 22,2883 483,2883 971,3371 1274,3674 1274,4735 1209,4800 1197,4800 70,4800 1,4731 1,2901 19,2883
5V on Top Layer "PWR Layer-No Net" (solid, remove dead copper, pour order 433): 5911.36,4434 6052.38,4434 6101.68,4483.3 6251.7,4483.3 6301,4434 6301,4322 6421,4202 6421,4102 6421,4048 6391,4018 6382,4009 6342,4009 6297,4009 6274,4032 6243,4063 6243,4253.98 6209.98,4287 6162,4287 6153.66,4295.34 6153.66,4337.3 6137.66,4353.3 5907.3,4353.3 5907,4429.64
PGND on Top Layer "PWR Layer-No Net" (solid, remove dead copper, pour order 436): 6511.91,4278.57 6667.91,4278.57 6685.91,4296.57 6685.91,4636.57 6523.48,4799 6056,4799 5895,4638 5895,4530 5901,4524 5901,4496 5901,4460.61 5906.61,4455 6034,4455 6102.57,4523.57 6448.91,4523.57 6497.91,4474.57 6497.91,4292.57
+2.5V on Top Layer "12" (solid, pour order 423): 4109,2258 4051,2200 4051,2177 4113,2115 4118,2115 4187,2184 4187,2201 4168,2220 4168,2225 4176,2233 4176,2239 4157,2258
+3.3VLMK on Top Layer "12" (solid, pour order 427): 5345,2270 5345,2277 5353,2285 5455,2285 5467,2273 5467,2136 5467,2100 5462,2095 5353,2095 5345,2103
+2.5V on Top Layer "12" (solid, pour order 428): 5270,2134 5234,2134 5222,2122 5218,2118 5152,2118 5133,2137 5130,2140 5100,2140 5026,2140 5018,2148 5018,2203 5022,2207 5129,2207 5165,2171 5263,2171 5266,2168 5270,2164 5270,2135
+3.3VLMK on PWR Layer "h" (solid, remove dead copper, pour order 432): 2284,4539 2238.47,4493.47 2238.47,4208.47 1772.83,3742.83 1772.83,2727.17 1895,2605 1895,2555 1895,1684 2334,1245 2334,79 2356,57 4643,57 4677.5,91.5 4677.5,685.83 4949,957.33 4949,1126.4 5245,1422.4 5245,1830 5305,1890 5653,1890 5704.5,1941.5 5704.5,2464.5 5674.09,2494.91 5170.09,2494.91 5045,2620 5045,2851 5213,3019 5213,3387.65 5188.54,3412.11 4388.39,3412.11 4328.5,3472 4328.5,4458 4247.5,4539
VDDD33 on PWR Layer "PWR Layer-No Net" (solid, remove dead copper, pour order 413): 5318.31,1873 6803,1873 6825,1851 6825,144 6740,59 4738,59 4705,92 4705,676 4955,926 4970,941 4970,1131 5275,1436 5275,1829.69 5312.97,1867.66
GND on PWR Layer "12" (solid, pour order 416): 4883,1728 4717,1562 4639,1562 4043.3,2157.7 4043.3,2221.14 4043.3,2245.01 4006.27,2282.04 4001.31,2287 3917,2287 3801,2287 3734,2354 3706,2382 3676,2382 3672,2382 3667,2387 3667,2414 3719,2466 4335,2466 4397,2404 4397,2190 4557,2030 4620,1967 4681,1967 4888,1760 4888,1733
+3.3V_LMX on PWR Layer "h" (solid, remove dead copper, pour order 431): 2312,82 2285,55 91,55 41,105 41,5007 91,5057 2180,5057 2211.14,5025.86 2211.14,4226.14 1750,3765 1750,2720.5 1881,2589.5 1881,1665 2312,1234 2312,82 2285,55
+3.3V_VCO on PWR Layer "PWR Layer-No Net" (solid, remove dead copper, pour order 424): 5197,2519 5773,2519 5815,2561 5815,3503 5792,3526 5671,3526 5661,3516 5661,3425 5648.09,3412.09 5241.09,3412.09 5234,3405 5234,3388 5234,2998 5106,2870 5075.5,2839.5 5075.5,2640.5
+3.3V_ALL on PWR Layer "h" (solid, remove dead copper, pour order 412): 5295.5,3432.5 4969.5,3432.5 4405.5,3432.5 4348.5,3489.5 4348.5,4485 4405.5,4542 5296,4542 5378,4460 5378,3515
5VIN on PWR Layer "PWR Layer-No Net" (solid, remove dead copper, pour order 414): 5839,1981 5927,1893 6805,1893 6824,1912 6824,4941 6710,5055 2299,5055 2252,5008 2252,4637.76 2314.76,4575 5368,4575 5407,4536 5407,3576 5432,3551 5825,3551 5839,3537
no net on Top Solder "h" (solid, pour order 58): 9.8,1616.96 467.8,1616.96 528.06,1677.22 528.06,1958.66 540.55,1971.15 600.71,1971.15 618.72,1953.14 618.72,1697.62 680.24,1636.1 832.52,1483.82 832.52,1325.6 832.52,1045.74 871.86,1006.4 913.6,1006.74 934.14,986.2 934.14,972.01 968.25,972.01 968.25,993.11 981.88,1006.74 1002.98,1006.74 1027,1030.76 1055.24,1059 1055.24,1099.89 1072.28,1116.92 1072.28,1939.06 960.24,2051.1 803.12,2208.22 384.4,2208.22 4.91,2208.22 -0.43,2202.88 -0.43,2139.42 2.89,2136.1 201.24,2136.1 205.24,2140.1 297.24,2140.1 330.24,2140.1 360.06,2103.22 382.31,2125.47 765.38,2125.47 994.58,1896.27 994.58,1053.2 978.35,1036.97 922.62,1036.97 914.24,1045.34 914.24,1061.1 914.24,1088.1 908.24,1094.1 908.24,1520.1 819.24,1609.1 699.24,1729.1 699.24,1995.1 650.38,2043.96 476.14,2043.96 447.73,2015.55 447.73,1971.15 447.73,1714.25 425.41,1691.93 1.07,1691.93 0.24,1691.1 0.24,1647.1 0.24,1626.52
no net on Top Solder "h" (solid): 368.09,2122.99 368.09,2139.68 362.68,2145.1 296.24,2145.1 305.43,2135.91 305.43,2122.99 305.43,1704.29 263.24,1662.1 407.24,1662.1 368.24,1701.1 368.24,1730.1 368.24,2125.13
